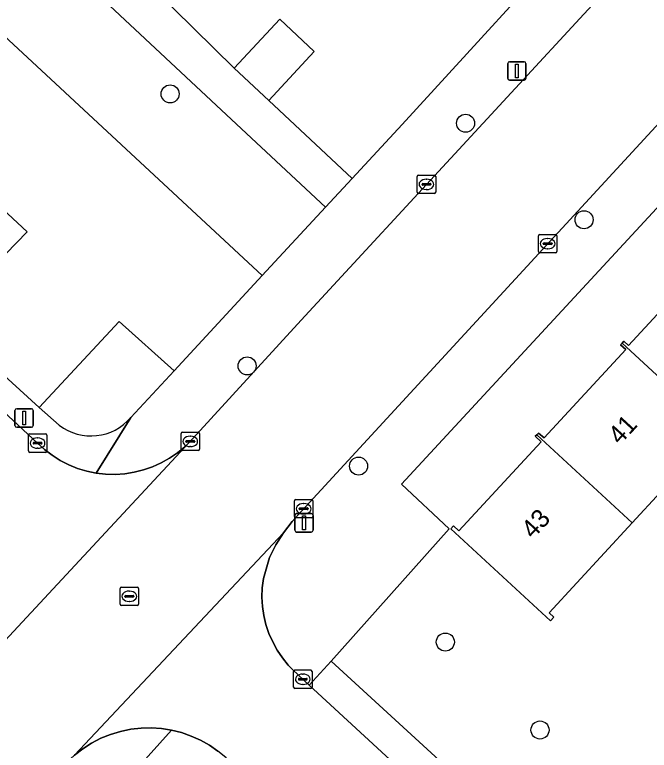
# Model space of a CAD drawing. Extents: x 159217 to 160349, y 381246 to 382172.
# Drawn here: x 159819.61 to 159854, y 381586.33 to 381626.21 of the extents above; entities that cross this region are included whole.
import ezdxf

# ---------------------------------------------------------------- set-up
doc = ezdxf.new("R2010")
doc.units = 0
for name, color, linetype in [('IMGEO_Boom', 7, 'Continuous'), ('IMGEO_Erf', 7, 'Continuous'), ('IMGEO_Groenvoorziening', 7, 'Continuous'), ('IMGEO_Kolk', 7, 'Continuous'), ('IMGEO_Lichtmast', 7, 'Continuous'), ('IMGEO_Pand', 7, 'Continuous'), ('IMGEO_Pand_nummerreeks', 7, 'Continuous'), ('IMGEO_Rijbaan_lokaal_open', 7, 'Continuous'), ('IMGEO_Rioolput', 7, 'Continuous'), ('IMGEO_Voetpad_open', 7, 'Continuous')]:
    doc.layers.add(name, color=color, linetype=linetype)

msp = doc.modelspace()

# ---------------------------------------------------------------- linework, layer by layer
at = {"layer": 'IMGEO_Boom'}
for centre in [(159828.037, 381621.916), (159844.044, 381620.323), (159850.466, 381615.092), (159832.21, 381607.17), (159838.245, 381601.737), (159842.95, 381592.2), (159848.08, 381587.43)]:
    msp.add_circle(centre, 0.489, dxfattribs=at)
at = {"layer": 'IMGEO_Erf'}
for points in [[(159817.734, 381635.572), (159821.799, 381632.312), (159823.411, 381634.164), (159826.008, 381631.753), (159828.244, 381629.677), (159828.62, 381629.328), (159827.134, 381627.623), (159831.5, 381623.317), (159833.974, 381625.968), (159835.85, 381624.217), (159833.376, 381621.566), (159837.909, 381617.335), (159840.613, 381620.254), (159850.934, 381631.546), (159807.485, 381672.085)], [(159891.859, 381656.228), (159840.577, 381600.766), (159843.162, 381598.335), (159836.759, 381591.155), (159854.989, 381574.45), (159863.492, 381583.729), (159861.622, 381585.458), (159864.266, 381588.318), (159866.785, 381591.042), (159868.655, 381589.313), (159872.741, 381593.716), (159870.871, 381595.445), (159873.515, 381598.305), (159876.034, 381601.029), (159877.904, 381599.3), (159881.961, 381603.666), (159884.605, 381606.525), (159884.405, 381606.71), (159882.189, 381604.314), (159880.519, 381605.858), (159882.735, 381608.254), (159885.254, 381610.979)], [(159857.689, 381603.647), (159853.078, 381598.662), (159848.575, 381593.791), (159848.836, 381593.551), (159848.643, 381593.343), (159843.24, 381598.339), (159843.388, 381598.499), (159843.68, 381598.228), (159848.141, 381603.053), (159847.814, 381603.355), (159847.91, 381603.44), (159848.007, 381603.525), (159848.301, 381603.262), (159852.728, 381608.05), (159852.446, 381608.31), (159852.538, 381608.41), (159852.629, 381608.508), (159852.885, 381608.27), (159857.346, 381613.094)]]:
    msp.add_lwpolyline(points, dxfattribs=at)
at = {"layer": 'IMGEO_Groenvoorziening'}
for points in [[(159831.37, 381620.522), (159810.981, 381639.573), (159798.344, 381625.917), (159802.529, 381622.003), (159811.633, 381631.939), (159833.028, 381612.068), (159836.458, 381615.77)], [(159811.633, 381631.939), (159802.529, 381622.003), (159811.692, 381613.435), (159816.102, 381618.314), (159820.288, 381614.431), (159815.676, 381609.71), (159820.934, 381604.918), (159825.276, 381609.576), (159828.247, 381606.909), (159833.028, 381612.068)], [(159811.692, 381613.435), (159815.676, 381609.71), (159820.288, 381614.431), (159816.102, 381618.314)]]:
    msp.add_lwpolyline(points, close=True, dxfattribs=at)
for points in [[(159828.247, 381606.909), (159825.276, 381609.576), (159820.934, 381604.918), (159822.03, 381603.951)], [(159825.907, 381604.369), (159828.247, 381606.909)]]:
    msp.add_lwpolyline(points, dxfattribs=at)
msp.add_arc((159823.747, 381606.21), 2.838, 232.7554, 319.5518, dxfattribs=at)
at = {"layer": 'IMGEO_Kolk'}
for p, q in [((159841.427, 381616.585), (159841.427, 381617.437)), ((159841.502, 381617.511), (159842.354, 381617.511)), ((159842.428, 381617.437), (159842.428, 381616.585)), ((159841.686, 381617.005), (159841.686, 381617.017)), ((159841.729, 381617.054), (159842.127, 381617.054)), ((159841.915, 381617.291), (159841.94, 381617.291)), ((159842.17, 381617.017), (159842.17, 381617.005)), ((159842.124, 381616.968), (159841.726, 381616.968)), ((159841.938, 381616.731), (159841.913, 381616.731)), ((159842.354, 381616.511), (159841.502, 381616.511)), ((159847.996, 381613.37), (159847.996, 381614.222)), ((159848.071, 381614.296), (159848.923, 381614.296)), ((159848.997, 381614.222), (159848.997, 381613.37)), ((159848.255, 381613.79), (159848.255, 381613.802)), ((159848.298, 381613.839), (159848.696, 381613.839)), ((159848.484, 381614.076), (159848.509, 381614.076)), ((159848.739, 381613.802), (159848.739, 381613.79)), ((159848.693, 381613.753), (159848.295, 381613.753)), ((159848.507, 381613.516), (159848.482, 381613.516)), ((159848.923, 381613.296), (159848.071, 381613.296)), ((159820.427, 381603.483), (159821.279, 381603.483)), ((159828.625, 381602.649), (159828.625, 381603.501)), ((159828.7, 381603.575), (159829.552, 381603.575)), ((159829.626, 381603.501), (159829.626, 381602.649)), ((159820.352, 381602.557), (159820.352, 381603.409)), ((159820.654, 381603.026), (159821.052, 381603.026)), ((159820.84, 381603.263), (159820.865, 381603.263)), ((159821.353, 381603.409), (159821.353, 381602.557)), ((159828.884, 381603.069), (159828.884, 381603.081)), ((159829.322, 381603.032), (159828.924, 381603.032)), ((159828.927, 381603.118), (159829.325, 381603.118)), ((159829.113, 381603.355), (159829.138, 381603.355)), ((159829.368, 381603.081), (159829.368, 381603.069)), ((159820.611, 381602.977), (159820.611, 381602.989)), ((159821.049, 381602.94), (159820.651, 381602.94)), ((159820.863, 381602.703), (159820.838, 381602.703)), ((159821.095, 381602.989), (159821.095, 381602.977)), ((159829.136, 381602.795), (159829.111, 381602.795)), ((159821.279, 381602.483), (159820.427, 381602.483)), ((159829.552, 381602.575), (159828.7, 381602.575)), ((159834.771, 381599), (159834.771, 381599.852)), ((159834.846, 381599.926), (159835.698, 381599.926)), ((159835.772, 381599.852), (159835.772, 381599)), ((159835.03, 381599.42), (159835.03, 381599.432)), ((159835.073, 381599.469), (159835.471, 381599.469)), ((159835.259, 381599.706), (159835.284, 381599.706)), ((159835.514, 381599.432), (159835.514, 381599.42)), ((159835.468, 381599.383), (159835.07, 381599.383)), ((159835.282, 381599.146), (159835.257, 381599.146)), ((159835.698, 381598.926), (159834.846, 381598.926)), ((159834.801, 381590.684), (159835.653, 381590.684)), ((159834.726, 381589.758), (159834.726, 381590.61)), ((159835.214, 381590.464), (159835.239, 381590.464)), ((159835.727, 381590.61), (159835.727, 381589.758)), ((159834.985, 381590.178), (159834.985, 381590.19)), ((159835.423, 381590.141), (159835.025, 381590.141)), ((159835.028, 381590.227), (159835.426, 381590.227)), ((159835.237, 381589.904), (159835.212, 381589.904)), ((159835.469, 381590.19), (159835.469, 381590.178)), ((159835.653, 381589.684), (159834.801, 381589.684))]:
    msp.add_line(p, q, dxfattribs=at)
for points in [[(159841.427, 381616.585), (159841.427, 381617.437)], [(159841.502, 381617.511), (159842.354, 381617.511)], [(159842.428, 381617.437), (159842.428, 381616.585)], [(159842.354, 381616.511), (159841.502, 381616.511)], [(159847.996, 381613.37), (159847.996, 381614.222)], [(159848.071, 381614.296), (159848.923, 381614.296)], [(159848.997, 381614.222), (159848.997, 381613.37)], [(159848.923, 381613.296), (159848.071, 381613.296)], [(159820.427, 381603.483), (159821.279, 381603.483)], [(159828.625, 381602.649), (159828.625, 381603.501)], [(159828.7, 381603.575), (159829.552, 381603.575)], [(159829.626, 381603.501), (159829.626, 381602.649)], [(159820.352, 381602.557), (159820.352, 381603.409)], [(159821.353, 381603.409), (159821.353, 381602.557)], [(159821.279, 381602.483), (159820.427, 381602.483)], [(159829.552, 381602.575), (159828.7, 381602.575)], [(159834.771, 381599), (159834.771, 381599.852)], [(159834.846, 381599.926), (159835.698, 381599.926)], [(159835.772, 381599.852), (159835.772, 381599)], [(159835.698, 381598.926), (159834.846, 381598.926)], [(159834.801, 381590.684), (159835.653, 381590.684)], [(159834.726, 381589.758), (159834.726, 381590.61)], [(159835.727, 381590.61), (159835.727, 381589.758)], [(159835.653, 381589.684), (159834.801, 381589.684)]]:
    msp.add_lwpolyline(points, dxfattribs=at)
for centre, radius, start, end in [((159841.504, 381617.435), 0.0765, 91.552, 178.448), ((159841.504, 381617.435), 0.0765, 91.552, 178.448), ((159842.352, 381617.435), 0.0765, 1.552, 88.448), ((159842.352, 381617.435), 0.0765, 1.552, 88.448), ((159841.726, 381617.014), 0.0403, 85.8775, 175.7526), ((159841.723, 381617.004), 0.0366, 178.938, 274.7102), ((159842.127, 381617.011), 0.043, 264.8664, 352.4533), ((159842.131, 381617.016), 0.0386, 1.7309, 96.639), ((159841.504, 381616.587), 0.0765, 181.552, 268.448), ((159841.504, 381616.587), 0.0765, 181.552, 268.448), ((159842.352, 381616.587), 0.0765, 271.552, 358.448), ((159842.352, 381616.587), 0.0765, 271.552, 358.448), ((159848.073, 381614.22), 0.0765, 91.552, 178.448), ((159848.073, 381614.22), 0.0765, 91.552, 178.448), ((159848.921, 381614.22), 0.0765, 1.552, 88.448), ((159848.921, 381614.22), 0.0765, 1.552, 88.448), ((159848.295, 381613.799), 0.0403, 85.8775, 175.7526), ((159848.292, 381613.789), 0.0366, 178.938, 274.7102), ((159848.696, 381613.796), 0.043, 264.8664, 352.4533), ((159848.7, 381613.801), 0.0386, 1.7309, 96.639), ((159848.073, 381613.372), 0.0765, 181.552, 268.448), ((159848.073, 381613.372), 0.0765, 181.552, 268.448), ((159848.921, 381613.372), 0.0765, 271.552, 358.448), ((159848.921, 381613.372), 0.0765, 271.552, 358.448), ((159820.429, 381603.407), 0.0765, 91.552, 178.448), ((159820.429, 381603.407), 0.0765, 91.552, 178.448), ((159821.277, 381603.407), 0.0765, 1.552, 88.448), ((159821.277, 381603.407), 0.0765, 1.552, 88.448), ((159828.702, 381603.499), 0.0765, 91.552, 178.448), ((159828.702, 381603.499), 0.0765, 91.552, 178.448), ((159829.55, 381603.499), 0.0765, 1.552, 88.448), ((159829.55, 381603.499), 0.0765, 1.552, 88.448), ((159820.651, 381602.986), 0.0403, 85.8775, 175.7526), ((159821.056, 381602.988), 0.0386, 1.7309, 96.639), ((159828.924, 381603.078), 0.0403, 85.8775, 175.7526), ((159828.921, 381603.068), 0.0366, 178.938, 274.7102), ((159829.325, 381603.075), 0.043, 264.8664, 352.4533), ((159829.329, 381603.08), 0.0386, 1.7309, 96.639), ((159820.648, 381602.976), 0.0366, 178.938, 274.7102), ((159821.052, 381602.983), 0.043, 264.8664, 352.4533), ((159828.702, 381602.651), 0.0765, 181.552, 268.448), ((159828.702, 381602.651), 0.0765, 181.552, 268.448), ((159829.55, 381602.651), 0.0765, 271.552, 358.448), ((159829.55, 381602.651), 0.0765, 271.552, 358.448), ((159820.429, 381602.559), 0.0765, 181.552, 268.448), ((159820.429, 381602.559), 0.0765, 181.552, 268.448), ((159821.277, 381602.559), 0.0765, 271.552, 358.448), ((159821.277, 381602.559), 0.0765, 271.552, 358.448), ((159834.848, 381599.85), 0.0765, 91.552, 178.448), ((159834.848, 381599.85), 0.0765, 91.552, 178.448), ((159835.696, 381599.85), 0.0765, 1.552, 88.448), ((159835.696, 381599.85), 0.0765, 1.552, 88.448), ((159835.07, 381599.429), 0.0403, 85.8775, 175.7526), ((159835.475, 381599.431), 0.0386, 1.7309, 96.639), ((159835.067, 381599.419), 0.0366, 178.938, 274.7102), ((159835.471, 381599.426), 0.043, 264.8664, 352.4533), ((159834.848, 381599.002), 0.0765, 181.552, 268.448), ((159834.848, 381599.002), 0.0765, 181.552, 268.448), ((159835.696, 381599.002), 0.0765, 271.552, 358.448), ((159835.696, 381599.002), 0.0765, 271.552, 358.448), ((159834.803, 381590.608), 0.0765, 91.552, 178.448), ((159834.803, 381590.608), 0.0765, 91.552, 178.448), ((159835.651, 381590.608), 0.0765, 1.552, 88.448), ((159835.651, 381590.608), 0.0765, 1.552, 88.448), ((159835.025, 381590.187), 0.0403, 85.8775, 175.7526), ((159835.022, 381590.177), 0.0366, 178.938, 274.7102), ((159835.426, 381590.184), 0.043, 264.8664, 352.4533), ((159835.43, 381590.189), 0.0386, 1.7309, 96.639), ((159834.803, 381589.76), 0.0765, 181.552, 268.448), ((159834.803, 381589.76), 0.0765, 181.552, 268.448), ((159835.651, 381589.76), 0.0765, 271.552, 358.448), ((159835.651, 381589.76), 0.0765, 271.552, 358.448)]:
    msp.add_arc(centre, radius, start, end, dxfattribs=at)
for centre, major_axis, ratio, start_param, end_param in [((159841.914, 381617.011), (-0.387, 0.002), 0.722429, 4.712389, 7.853982), ((159841.939, 381617.011), (-0.39, 0.002), 0.717154, 1.570796, 4.712389), ((159848.483, 381613.796), (-0.387, 0.002), 0.722429, 4.712389, 7.853982), ((159848.508, 381613.796), (-0.39, 0.002), 0.717154, 1.570796, 4.712389), ((159820.839, 381602.983), (-0.387, 0.002), 0.722429, 4.712389, 7.853982), ((159820.864, 381602.983), (-0.39, 0.002), 0.717154, 1.570796, 4.712389), ((159829.112, 381603.075), (-0.387, 0.002), 0.722429, 4.712389, 7.853982), ((159829.137, 381603.075), (-0.39, 0.002), 0.717154, 1.570796, 4.712389), ((159835.258, 381599.426), (-0.387, 0.002), 0.722429, 4.712389, 7.853982), ((159835.283, 381599.426), (-0.39, 0.002), 0.717154, 1.570796, 4.712389), ((159835.213, 381590.184), (-0.387, 0.002), 0.722429, 4.712389, 7.853982), ((159835.238, 381590.184), (-0.39, 0.002), 0.717154, 1.570796, 4.712389)]:
    msp.add_ellipse(centre, major_axis=major_axis, ratio=ratio, start_param=start_param, end_param=end_param, dxfattribs=at)
at = {"layer": 'IMGEO_Lichtmast'}
for p, q in [((159846.329, 381622.758), (159846.329, 381623.558)), ((159846.329, 381623.558), (159846.329, 381622.758)), ((159846.429, 381623.658), (159847.219, 381623.658)), ((159847.219, 381623.658), (159846.429, 381623.658)), ((159847.319, 381623.558), (159847.319, 381622.758)), ((159847.319, 381622.758), (159847.319, 381623.558)), ((159847.219, 381622.658), (159846.429, 381622.658)), ((159846.429, 381622.658), (159847.219, 381622.658)), ((159819.628, 381603.945), (159819.628, 381604.745)), ((159819.628, 381604.745), (159819.628, 381603.945)), ((159819.728, 381604.845), (159820.518, 381604.845)), ((159820.518, 381604.845), (159819.728, 381604.845)), ((159820.618, 381604.745), (159820.618, 381603.945)), ((159820.618, 381603.945), (159820.618, 381604.745)), ((159820.518, 381603.845), (159819.728, 381603.845)), ((159819.728, 381603.845), (159820.518, 381603.845)), ((159834.793, 381598.259), (159834.793, 381599.059)), ((159834.793, 381599.059), (159834.793, 381598.259)), ((159834.893, 381599.159), (159835.683, 381599.159)), ((159835.683, 381599.159), (159834.893, 381599.159)), ((159835.783, 381599.059), (159835.783, 381598.259)), ((159835.783, 381598.259), (159835.783, 381599.059)), ((159835.683, 381598.159), (159834.893, 381598.159)), ((159834.893, 381598.159), (159835.683, 381598.159))]:
    msp.add_line(p, q, dxfattribs=at)
for points in [[(159846.749, 381623.533), (159846.899, 381623.533), (159846.899, 381622.783), (159846.749, 381622.783), (159846.749, 381623.533)], [(159820.048, 381604.72), (159820.198, 381604.72), (159820.198, 381603.97), (159820.048, 381603.97), (159820.048, 381604.72)], [(159835.213, 381599.034), (159835.363, 381599.034), (159835.363, 381598.284), (159835.213, 381598.284), (159835.213, 381599.034)]]:
    msp.add_lwpolyline(points, dxfattribs=at)
for centre, start, end in [((159846.429, 381623.558), 90, 180), ((159846.429, 381623.558), 90, 180), ((159847.219, 381623.558), 0, 90), ((159847.219, 381623.558), 360, 90), ((159846.429, 381622.758), 180, 270), ((159846.429, 381622.758), 180, 270), ((159847.219, 381622.758), 270, 0), ((159847.219, 381622.758), 270, 0), ((159819.728, 381604.745), 90, 180), ((159819.728, 381604.745), 90, 180), ((159820.518, 381604.745), 0, 90), ((159820.518, 381604.745), 360, 90), ((159819.728, 381603.945), 180, 270), ((159819.728, 381603.945), 180, 270), ((159820.518, 381603.945), 270, 0), ((159820.518, 381603.945), 270, 0), ((159834.893, 381599.059), 90, 180), ((159834.893, 381599.059), 90, 180), ((159835.683, 381599.059), 0, 90), ((159835.683, 381599.059), 360, 90), ((159834.893, 381598.259), 180, 270), ((159834.893, 381598.259), 180, 270), ((159835.683, 381598.259), 270, 0), ((159835.683, 381598.259), 270, 0)]:
    msp.add_arc(centre, 0.1, start, end, dxfattribs=at)
at = {"layer": 'IMGEO_Pand'}
for points in [[(159833.376, 381621.566), (159835.85, 381624.217), (159833.974, 381625.968), (159831.5, 381623.317)], [(159862.319, 381608.656), (159857.163, 381613.423), (159857.083, 381613.337), (159857.346, 381613.094), (159852.885, 381608.27), (159852.629, 381608.508), (159852.538, 381608.41), (159857.689, 381603.647)], [(159853.078, 381598.662), (159857.689, 381603.647), (159852.538, 381608.41), (159852.446, 381608.31), (159852.728, 381608.05), (159848.301, 381603.262), (159848.007, 381603.525), (159847.91, 381603.44)], [(159853.078, 381598.662), (159847.91, 381603.44), (159847.814, 381603.355), (159848.141, 381603.053), (159843.68, 381598.228), (159843.388, 381598.499), (159843.24, 381598.339), (159848.643, 381593.343), (159848.836, 381593.551), (159848.575, 381593.791)]]:
    msp.add_lwpolyline(points, close=True, dxfattribs=at)
at = {"layer": 'IMGEO_Rijbaan_lokaal_open'}
for points in [[(159853.087, 381629.109), (159835.145, 381609.655), (159829.069, 381603.011), (159817.636, 381590.721)], [(159804.623, 381566.347), (159822.289, 381585.535), (159822.436, 381585.689), (159822.853, 381586.072), (159834.176, 381598.121), (159834.644, 381598.738), (159835.165, 381599.311), (159838.508, 381602.939), (159860.89, 381627.268)], [(159817.636, 381590.721), (159829.069, 381603.011), (159828.833, 381602.785), (159828.433, 381602.455), (159828.006, 381602.162), (159827.554, 381601.908), (159827.082, 381601.696), (159826.592, 381601.527), (159826.089, 381601.402), (159825.577, 381601.322), (159825.06, 381601.289), (159824.542, 381601.302), (159824.027, 381601.361), (159823.52, 381601.466), (159823.024, 381601.616), (159822.543, 381601.81), (159822.082, 381602.045), (159821.643, 381602.321), (159821.231, 381602.635), (159820.849, 381602.985), (159799.503, 381622.862)], [(159840.646, 381585.172), (159835.569, 381589.866), (159834.683, 381590.686), (159834.435, 381590.949), (159834.117, 381591.341), (159833.836, 381591.76), (159833.593, 381592.202), (159833.391, 381592.664), (159833.231, 381593.143), (159833.114, 381593.634), (159833.041, 381594.133), (159833.014, 381594.637), (159833.031, 381595.141), (159833.094, 381595.642), (159833.422, 381596.79), (159833.765, 381597.464), (159834.176, 381598.121), (159822.853, 381586.072), (159823.301, 381586.416), (159823.779, 381586.719), (159824.282, 381586.979), (159824.806, 381587.192), (159825.346, 381587.357), (159825.909, 381587.475), (159826.461, 381587.537), (159827.016, 381587.549), (159827.57, 381587.511), (159828.118, 381587.424), (159828.656, 381587.289), (159829.181, 381587.105), (159829.686, 381586.876), (159830.169, 381586.603), (159830.626, 381586.287)]]:
    msp.add_lwpolyline(points, dxfattribs=at)
at = {"layer": 'IMGEO_Rioolput'}
for p, q in [((159825.327, 381594.252), (159825.327, 381595.104)), ((159825.402, 381595.178), (159826.254, 381595.178)), ((159826.328, 381595.104), (159826.328, 381594.252)), ((159825.586, 381594.672), (159825.586, 381594.684)), ((159825.629, 381594.721), (159826.027, 381594.721)), ((159825.815, 381594.958), (159825.84, 381594.958)), ((159826.07, 381594.684), (159826.07, 381594.672)), ((159826.024, 381594.635), (159825.626, 381594.635)), ((159825.838, 381594.398), (159825.813, 381594.398)), ((159826.254, 381594.178), (159825.402, 381594.178))]:
    msp.add_line(p, q, dxfattribs=at)
for points in [[(159825.327, 381594.252), (159825.327, 381595.104)], [(159825.402, 381595.178), (159826.254, 381595.178)], [(159826.328, 381595.104), (159826.328, 381594.252)], [(159826.254, 381594.178), (159825.402, 381594.178)]]:
    msp.add_lwpolyline(points, dxfattribs=at)
for centre, radius, start, end in [((159825.404, 381595.102), 0.0765, 91.552, 178.448), ((159825.404, 381595.102), 0.0765, 91.552, 178.448), ((159826.252, 381595.102), 0.0765, 1.552, 88.448), ((159826.252, 381595.102), 0.0765, 1.552, 88.448), ((159825.626, 381594.681), 0.0403, 85.8775, 175.7526), ((159825.623, 381594.671), 0.0366, 178.938, 274.7102), ((159826.027, 381594.678), 0.043, 264.8664, 352.4533), ((159826.031, 381594.683), 0.0386, 1.7309, 96.639), ((159825.404, 381594.254), 0.0765, 181.552, 268.448), ((159825.404, 381594.254), 0.0765, 181.552, 268.448), ((159826.252, 381594.254), 0.0765, 271.552, 358.448), ((159826.252, 381594.254), 0.0765, 271.552, 358.448)]:
    msp.add_arc(centre, radius, start, end, dxfattribs=at)
for centre, major_axis, ratio, start_param, end_param in [((159825.814, 381594.678), (-0.387, 0.002), 0.722429, 4.712389, 7.853982), ((159825.839, 381594.678), (-0.39, 0.002), 0.717154, 1.570796, 4.712389)]:
    msp.add_ellipse(centre, major_axis=major_axis, ratio=ratio, start_param=start_param, end_param=end_param, dxfattribs=at)
at = {"layer": 'IMGEO_Voetpad_open'}
for points in [[(159860.89, 381627.268), (159838.508, 381602.939), (159835.165, 381599.311), (159834.644, 381598.738), (159834.176, 381598.121), (159833.765, 381597.464), (159833.422, 381596.79), (159833.094, 381595.642), (159833.031, 381595.141), (159833.014, 381594.637), (159833.041, 381594.133), (159833.114, 381593.634), (159833.231, 381593.143), (159833.391, 381592.664), (159833.593, 381592.202), (159833.836, 381591.76), (159834.117, 381591.341), (159834.435, 381590.949), (159834.683, 381590.686), (159835.569, 381589.866), (159836.759, 381591.155), (159843.162, 381598.335), (159840.577, 381600.766), (159891.859, 381656.228)], [(159780.479, 381646.24), (159777.705, 381642.919), (159779.33, 381641.41), (159781.571, 381639.325), (159793.749, 381628.22), (159795.967, 381626.155), (159799.503, 381622.862), (159820.849, 381602.985), (159821.231, 381602.635), (159821.643, 381602.321), (159822.082, 381602.045), (159822.543, 381601.81), (159823.024, 381601.616), (159823.52, 381601.466), (159824.027, 381601.361), (159825.907, 381604.369)], [(159850.934, 381631.546), (159840.613, 381620.254), (159837.909, 381617.335), (159836.458, 381615.77), (159833.028, 381612.068), (159828.247, 381606.909), (159825.907, 381604.369), (159824.027, 381601.361), (159824.542, 381601.302), (159825.06, 381601.289), (159825.577, 381601.322), (159826.089, 381601.402), (159826.592, 381601.527), (159827.082, 381601.696), (159827.554, 381601.908), (159828.006, 381602.162), (159828.433, 381602.455), (159828.833, 381602.785), (159829.069, 381603.011), (159835.145, 381609.655), (159853.087, 381629.109)], [(159822.03, 381603.951), (159820.934, 381604.918), (159815.676, 381609.71), (159811.692, 381613.435), (159802.529, 381622.003)], [(159836.759, 381591.155), (159835.569, 381589.866), (159840.646, 381585.172), (159843.803, 381582.252), (159846.923, 381579.367), (159855.141, 381571.732), (159864.692, 381562.858), (159872.694, 381555.382), (159876.296, 381552.057), (159878.534, 381549.992), (159878.959, 381549.646), (159879.412, 381549.34), (159879.891, 381549.076), (159880.392, 381548.855), (159880.911, 381548.68), (159881.443, 381548.552), (159881.985, 381548.472), (159882.531, 381548.441), (159883.078, 381548.459), (159883.095, 381548.46)], [(159878.839, 381554.068), (159877.851, 381554.987), (159875.577, 381557.103), (159873.348, 381559.178), (159871.118, 381561.253), (159868.889, 381563.328), (159866.66, 381565.402), (159864.43, 381567.477), (159862.201, 381569.552), (159859.971, 381571.627), (159857.742, 381573.702), (159857.324, 381574.089), (159856.438, 381573.122), (159854.989, 381574.45), (159836.759, 381591.155)], [(159841.851, 381575.861), (159839.731, 381577.838), (159836.587, 381580.771), (159831.053, 381585.932), (159830.626, 381586.287), (159830.169, 381586.603), (159829.686, 381586.876), (159829.181, 381587.105), (159828.656, 381587.289), (159828.118, 381587.424), (159824.319, 381583.193)]]:
    msp.add_lwpolyline(points, dxfattribs=at)
for points in [[(159827.134, 381627.623), (159826.853, 381627.3), (159824.175, 381629.786), (159821.645, 381632.135), (159821.799, 381632.312), (159817.734, 381635.572), (159815.234, 381637.934), (159812.503, 381640.514), (159810.61, 381642.285), (159808.819, 381640.327), (159805.815, 381636.622), (159803.23, 381633.865), (159800.946, 381631.43), (159796.971, 381627.201), (159798.344, 381625.917), (159810.981, 381639.573), (159831.37, 381620.522), (159836.458, 381615.77), (159837.909, 381617.335), (159833.376, 381621.566), (159831.5, 381623.317)], [(159824.319, 381583.193), (159828.118, 381587.424), (159827.57, 381587.511), (159827.016, 381587.549), (159826.461, 381587.537), (159825.909, 381587.475), (159825.346, 381587.357), (159824.806, 381587.192), (159824.282, 381586.979), (159823.779, 381586.719), (159823.301, 381586.416), (159822.853, 381586.072), (159822.436, 381585.689), (159822.289, 381585.535), (159804.623, 381566.347), (159788.349, 381548.598), (159768.221, 381526.805), (159761.898, 381520.03), (159764.137, 381517.952)]]:
    msp.add_lwpolyline(points, close=True, dxfattribs=at)
msp.add_arc((159823.747, 381606.21), 2.838, 232.7554, 319.5518, dxfattribs=at)

# ---------------------------------------------------------------- texts
at = {"layer": 'IMGEO_Pand_nummerreeks'}
for s, p in [('41', (159852.408, 381602.846)), ('43', (159847.699, 381597.745))]:
    msp.add_text(s, height=1, rotation=47.2849, dxfattribs=at).set_placement(p)

doc.saveas('drawing.dxf')
